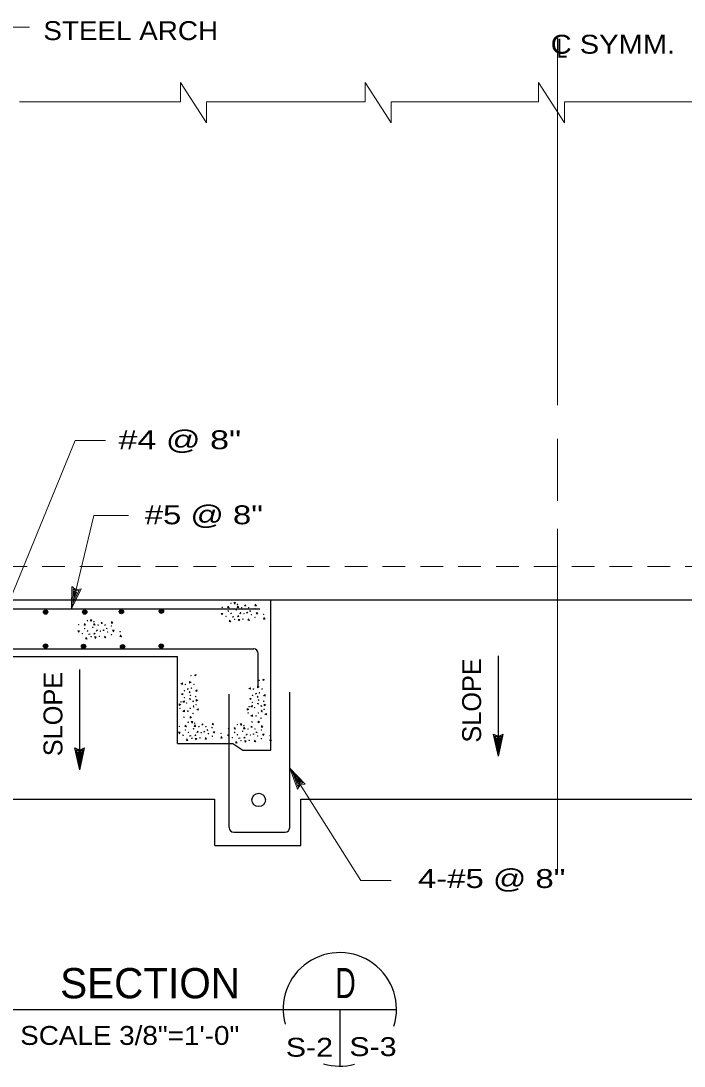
# Model space of a CAD drawing. Extents: x -28.1 to 13.9, y -16.1 to 13.9.
# Drawn here: x -19.31 to -14.93, y -7.92 to -1.02 of the extents above; entities that cross this region are included whole.
import ezdxf
from ezdxf.enums import TextEntityAlignment as Align

# ---------------------------------------------------------------- set-up
doc = ezdxf.new("R2010")
doc.units = 0
doc.header["$LTSCALE"] = 0.05
doc.linetypes.add('MEDIUM_DASHED', pattern=[4.5, 3, -1.5])
doc.layers.add('1', color=7, linetype='Continuous', lineweight=13)
doc.layers.add('2', color=7, linetype='Continuous', lineweight=13)

msp = doc.modelspace()

# ---------------------------------------------------------------- linework, layer by layer
at = {"layer": '1'}
for p, q in [((-15.76204, -3.55531), (-15.76204, -1.13031)), ((-18.25304, -1.55131), (-18.25304, -1.42331)), ((-18.08104, -1.68931), (-18.25304, -1.42331)), ((-17.03304, -1.55131), (-17.03304, -1.42331)), ((-16.86104, -1.68931), (-17.03304, -1.42331)), ((-15.88704, -1.55131), (-15.88704, -1.42331)), ((-15.71504, -1.68931), (-15.88704, -1.42331)), ((-18.25304, -1.55131), (-19.31704, -1.55131)), ((-18.08104, -1.68931), (-18.08104, -1.55131)), ((-17.03304, -1.55131), (-18.08104, -1.55131)), ((-16.86104, -1.68931), (-16.86104, -1.55131)), ((-15.88704, -1.55131), (-16.86104, -1.55131)), ((-15.71504, -1.68931), (-15.71504, -1.55131)), ((-14.65104, -1.55131), (-15.71504, -1.55131)), ((-19.39304, -4.87031), (-18.95004, -3.78931)), ((-18.95004, -3.78931), (-18.75004, -3.78931)), ((-15.76204, -4.18731), (-15.76204, -3.77831)), ((-18.97404, -4.90231), (-18.82604, -4.28531)), ((-18.82604, -4.28531), (-18.59704, -4.28531)), ((-15.76204, -6.64831), (-15.76204, -4.37331)), ((-18.97404, -4.90231), (-18.97104, -4.75531)), ((-18.97404, -4.90231), (-18.91004, -4.76931)), ((-18.96504, -4.86631), (-18.96304, -4.77031)), ((-18.96504, -4.86631), (-18.92404, -4.77931)), ((-18.96304, -4.77031), (-18.94604, -4.78331)), ((-18.95704, -4.83131), (-18.95604, -4.78531)), ((-18.95704, -4.83131), (-18.93804, -4.78931)), ((-18.95604, -4.78531), (-18.94704, -4.79131)), ((-18.94704, -4.79131), (-18.93804, -4.78931)), ((-18.94604, -4.78331), (-18.92404, -4.77931)), ((-17.53204, -5.95531), (-17.42904, -6.06031)), ((-17.53204, -5.95531), (-17.48104, -6.09331)), ((-17.51204, -5.98631), (-17.44504, -6.05531)), ((-17.51204, -5.98631), (-17.47904, -6.07631)), ((-17.49304, -6.01731), (-17.47604, -6.05931)), ((-17.49304, -6.01731), (-17.46004, -6.04931)), ((-17.46704, -6.05831), (-17.47904, -6.07631)), ((-17.47104, -6.05131), (-17.47604, -6.05931)), ((-17.46004, -6.04931), (-17.47104, -6.05131)), ((-17.44504, -6.05531), (-17.46704, -6.05831))]:
    msp.add_line(p, q, dxfattribs=at)
at = {"layer": '1', "linetype": 'MEDIUM_DASHED'}
msp.add_line((-20.41804, -4.62131), (-12.68204, -4.62131), dxfattribs=at)
at = {"layer": '1', "lineweight": 25}
for p, q in [((-21.29204, -4.84331), (-12.68604, -4.84331)), ((-20.51304, -4.90231), (-17.72904, -4.90231)), ((-17.65604, -5.83731), (-17.65604, -4.84331)), ((-21.29604, -5.16731), (-17.77004, -5.16731)), ((-23.96004, -5.21731), (-18.27404, -5.21731)), ((-18.27404, -5.79331), (-18.27404, -5.21731)), ((-17.74004, -5.41431), (-17.74004, -5.19731)), ((-16.15304, -5.87531), (-16.15304, -5.21231)), ((-18.92004, -5.96531), (-18.92004, -5.30231)), ((-17.53204, -6.34831), (-17.53204, -5.45231)), ((-17.93204, -6.34831), (-17.93204, -5.46631)), ((-16.15304, -5.87531), (-16.18404, -5.73131)), ((-16.15304, -5.87531), (-16.12204, -5.73131)), ((-18.27404, -5.79331), (-17.90704, -5.79331)), ((-17.90704, -5.79331), (-17.84104, -5.83731)), ((-16.15304, -5.83831), (-16.17304, -5.74431)), ((-16.17304, -5.74431), (-16.15304, -5.75331)), ((-16.15304, -5.80231), (-16.16304, -5.75731)), ((-16.16304, -5.75731), (-16.15304, -5.76131)), ((-16.15304, -5.83831), (-16.13304, -5.74431)), ((-16.15304, -5.75331), (-16.13304, -5.74431)), ((-16.15304, -5.80231), (-16.14404, -5.75731)), ((-16.15304, -5.76131), (-16.14404, -5.75731)), ((-18.92004, -5.96531), (-18.95104, -5.82131)), ((-18.92004, -5.92831), (-18.94004, -5.83431)), ((-18.94004, -5.83431), (-18.92004, -5.84331)), ((-18.92004, -5.89231), (-18.93004, -5.84731)), ((-18.93004, -5.84731), (-18.92004, -5.85131)), ((-18.92004, -5.96531), (-18.88904, -5.82131)), ((-18.92004, -5.92831), (-18.90004, -5.83431)), ((-18.92004, -5.84331), (-18.90004, -5.83431)), ((-18.92004, -5.89231), (-18.91104, -5.84731)), ((-18.92004, -5.85131), (-18.91104, -5.84731)), ((-17.84104, -5.83731), (-17.65604, -5.83731)), ((-21.29004, -6.16031), (-18.02804, -6.16031)), ((-18.02704, -6.46731), (-18.02704, -6.16031)), ((-17.90204, -6.37831), (-17.56204, -6.37831)), ((-18.02704, -6.46731), (-17.45804, -6.46731)), ((-19.53504, -7.54931), (-16.82604, -7.54931)), ((-17.20104, -7.54931), (-17.20104, -7.92431))]:
    msp.add_line(p, q, dxfattribs=at)
at = {"layer": '1'}
for points in [[(-20.42404, -2.50931), (-19.52504, -1.05831), (-19.25104, -1.05831)], [(-18.97104, -4.75531), (-18.94404, -4.77631), (-18.91004, -4.76931)], [(-17.53204, -5.95531), (-17.06104, -6.69731), (-16.86204, -6.69731)], [(-17.42904, -6.06031), (-17.46204, -6.06531), (-17.48104, -6.09331)]]:
    msp.add_lwpolyline(points, dxfattribs=at)
at = {"layer": '1', "lineweight": 25}
for points in [[(-16.18404, -5.73131), (-16.15304, -5.74531), (-16.12204, -5.73131)], [(-18.95104, -5.82131), (-18.92004, -5.83531), (-18.88904, -5.82131)], [(-17.45804, -6.46731), (-17.45804, -6.16031), (-14.06804, -6.16031)]]:
    msp.add_lwpolyline(points, dxfattribs=at)
for centre, radius in [((-18.37957, -4.91759), 0.01445), ((-19.14557, -4.92359), 0.01445), ((-19.14557, -4.92359), 0.01121), ((-19.14557, -4.92359), 0.00822), ((-19.14557, -4.92359), 0.00415), ((-18.88657, -4.92359), 0.01445), ((-18.88657, -4.92359), 0.01121), ((-18.88657, -4.92359), 0.00822), ((-18.88657, -4.92359), 0.00415), ((-18.64457, -4.92059), 0.01445), ((-18.64457, -4.92059), 0.01121), ((-18.64457, -4.92059), 0.00822), ((-18.64457, -4.92059), 0.00415), ((-18.37957, -4.91759), 0.01121), ((-18.37957, -4.91759), 0.00822), ((-18.37957, -4.91759), 0.00415), ((-19.14557, -5.14859), 0.01445), ((-19.14557, -5.14859), 0.01121), ((-19.14557, -5.14859), 0.00822), ((-19.14557, -5.14859), 0.00415), ((-18.89457, -5.15059), 0.01445), ((-18.89457, -5.15059), 0.01121), ((-18.89457, -5.15059), 0.00822), ((-18.89457, -5.15059), 0.00415), ((-18.63657, -5.15259), 0.01445), ((-18.63657, -5.15259), 0.01121), ((-18.63657, -5.15259), 0.00822), ((-18.63657, -5.15259), 0.00415), ((-18.38057, -5.14859), 0.01445), ((-18.38057, -5.14859), 0.01121), ((-18.38057, -5.14859), 0.00822), ((-18.38057, -5.14859), 0.00415), ((-17.73704, -6.16531), 0.04428)]:
    msp.add_circle(centre, radius, dxfattribs=at)
for centre, radius, start, end in [((-17.77004, -5.19731), 0.03, 0, 90), ((-17.90204, -6.34831), 0.03, 180, 270), ((-17.56204, -6.34831), 0.03, 270, 0), ((-17.20104, -7.54931), 0.375, 342.70891, 195.26862), ((-17.20104, -7.54931), 0.375, 253.4742, 284.92162)]:
    msp.add_arc(centre, radius, start, end, dxfattribs=at)
at = {"layer": '2'}
for p, q in [((-17.83004, -4.88131), (-17.82404, -4.87631)), ((-18.77904, -4.99631), (-18.77304, -4.99131)), ((-18.24104, -5.47031), (-18.24604, -5.46431)), ((-17.79104, -5.50131), (-17.79604, -5.49531)), ((-18.11304, -5.66731), (-18.10704, -5.66231)), ((-17.78804, -5.68331), (-17.78204, -5.67831))]:
    msp.add_line(p, q, dxfattribs=at)
for points in [[(-17.93704, -4.88431), (-17.94204, -4.89431), (-17.93204, -4.89531), (-17.94004, -4.88431)], [(-17.89604, -4.86931), (-17.90104, -4.86031), (-17.89004, -4.86031), (-17.89604, -4.87131)], [(-17.87504, -4.88331), (-17.88004, -4.89331), (-17.86904, -4.89431), (-17.87704, -4.88331)], [(-17.82404, -4.87631), (-17.82204, -4.88331), (-17.83004, -4.88331)], [(-17.75704, -4.87131), (-17.76204, -4.88131), (-17.75204, -4.88231), (-17.76004, -4.87131)], [(-17.97904, -4.94031), (-17.98404, -4.93231), (-17.97304, -4.93231), (-17.97904, -4.94231)], [(-17.91004, -4.95531), (-17.90504, -4.95231), (-17.90104, -4.95531), (-17.91304, -4.95731)], [(-17.86804, -4.98131), (-17.87304, -4.97231), (-17.86204, -4.97231), (-17.86804, -4.98231)], [(-17.81704, -4.92931), (-17.81404, -4.92531), (-17.80904, -4.92931), (-17.81604, -4.93031)], [(-17.80304, -4.96731), (-17.80804, -4.97731), (-17.79804, -4.97831), (-17.80604, -4.96731)], [(-17.79704, -4.91631), (-17.79204, -4.91431), (-17.78904, -4.92031), (-17.79704, -4.91731)], [(-17.74904, -4.93631), (-17.75404, -4.92831), (-17.74304, -4.92831), (-17.74904, -4.93831)], [(-17.70004, -4.96031), (-17.70504, -4.97031), (-17.69504, -4.97131), (-17.70204, -4.96031)], [(-18.88604, -4.99931), (-18.89104, -5.00931), (-18.88104, -5.01031), (-18.88904, -4.99931)], [(-18.84504, -4.98431), (-18.85004, -4.97531), (-18.83904, -4.97531), (-18.84504, -4.98631)], [(-18.82404, -4.99831), (-18.82904, -5.00831), (-18.81804, -5.00931), (-18.82604, -4.99831)], [(-18.77304, -4.99131), (-18.77104, -4.99831), (-18.77904, -4.99831)], [(-18.76604, -5.04431), (-18.76304, -5.04031), (-18.75804, -5.04431), (-18.76504, -5.04531)], [(-18.74604, -5.03131), (-18.74104, -5.02931), (-18.73804, -5.03531), (-18.74604, -5.03231)], [(-18.70604, -4.98631), (-18.71104, -4.99631), (-18.70104, -4.99731), (-18.70904, -4.98631)], [(-17.92704, -4.97631), (-17.93204, -4.98631), (-17.92204, -4.98731), (-17.93004, -4.97631)], [(-18.92804, -5.05531), (-18.93304, -5.04731), (-18.92204, -5.04731), (-18.92804, -5.05731)], [(-18.87604, -5.09131), (-18.88104, -5.10131), (-18.87104, -5.10231), (-18.87904, -5.09131)], [(-18.85904, -5.07031), (-18.85404, -5.06731), (-18.85004, -5.07031), (-18.86204, -5.07231)], [(-18.81704, -5.09631), (-18.82204, -5.08731), (-18.81104, -5.08731), (-18.81704, -5.09731)], [(-18.75204, -5.08231), (-18.75704, -5.09231), (-18.74704, -5.09331), (-18.75504, -5.08231)], [(-18.69804, -5.05131), (-18.70304, -5.04331), (-18.69204, -5.04331), (-18.69804, -5.05331)], [(-18.64904, -5.07531), (-18.65404, -5.08531), (-18.64404, -5.08631), (-18.65104, -5.07531)], [(-18.18604, -5.38931), (-18.19404, -5.39431), (-18.19404, -5.38331), (-18.18404, -5.38931)], [(-18.16204, -5.34031), (-18.15204, -5.34531), (-18.15104, -5.33531), (-18.16204, -5.34231)], [(-17.71204, -5.37131), (-17.70204, -5.37631), (-17.70104, -5.36631), (-17.71204, -5.37331)], [(-18.25104, -5.39731), (-18.24104, -5.40231), (-18.24004, -5.39231), (-18.25104, -5.40031)], [(-18.20604, -5.43731), (-18.20804, -5.43231), (-18.20204, -5.42931), (-18.20504, -5.43731)], [(-18.19304, -5.45731), (-18.19704, -5.45431), (-18.19304, -5.44931), (-18.19204, -5.45631)], [(-18.15504, -5.44331), (-18.14504, -5.44831), (-18.14404, -5.43831), (-18.15504, -5.44631)], [(-17.80104, -5.42831), (-17.79104, -5.43331), (-17.79004, -5.42331), (-17.80104, -5.43131)], [(-17.73604, -5.42031), (-17.74404, -5.42531), (-17.74404, -5.41431), (-17.73404, -5.42031)], [(-18.24604, -5.46431), (-18.23904, -5.46231), (-18.23904, -5.47031)], [(-18.23904, -5.51531), (-18.22904, -5.52031), (-18.22804, -5.50931), (-18.23904, -5.51731)], [(-18.14104, -5.50831), (-18.15004, -5.51331), (-18.15004, -5.50231), (-18.14004, -5.50831)], [(-17.79604, -5.49531), (-17.78904, -5.49331), (-17.78904, -5.50131)], [(-17.75604, -5.46831), (-17.75804, -5.46331), (-17.75204, -5.46031), (-17.75504, -5.46831)], [(-17.74304, -5.48831), (-17.74704, -5.48531), (-17.74304, -5.48031), (-17.74204, -5.48731)], [(-17.70504, -5.47431), (-17.69504, -5.47931), (-17.69404, -5.46931), (-17.70504, -5.47731)], [(-18.25304, -5.53631), (-18.26204, -5.54131), (-18.26204, -5.53031), (-18.25104, -5.53631)], [(-18.23804, -5.57731), (-18.22804, -5.58231), (-18.22704, -5.57231), (-18.23804, -5.58031)], [(-18.16704, -5.55031), (-18.17004, -5.54531), (-18.16704, -5.54131), (-18.16504, -5.55331)], [(-18.14604, -5.56731), (-18.13604, -5.57231), (-18.13504, -5.56231), (-18.14604, -5.57031)], [(-17.80304, -5.56731), (-17.81204, -5.57231), (-17.81204, -5.56131), (-17.80104, -5.56731)], [(-17.78904, -5.54631), (-17.77904, -5.55131), (-17.77804, -5.54031), (-17.78904, -5.54831)], [(-17.71704, -5.58131), (-17.72004, -5.57631), (-17.71704, -5.57231), (-17.71504, -5.58431)], [(-17.69104, -5.53931), (-17.70004, -5.54431), (-17.70004, -5.53331), (-17.69004, -5.53931)], [(-17.69604, -5.59831), (-17.68604, -5.60331), (-17.68504, -5.59331), (-17.69604, -5.60131)], [(-18.18204, -5.61931), (-18.19004, -5.62431), (-18.19004, -5.61331), (-18.18004, -5.61931)], [(-18.17904, -5.65531), (-18.18404, -5.64631), (-18.17304, -5.64631), (-18.17904, -5.65731)], [(-18.10704, -5.66231), (-18.10504, -5.66931), (-18.11304, -5.66931)], [(-18.04004, -5.65731), (-18.04504, -5.66731), (-18.03504, -5.66831), (-18.04304, -5.65731)], [(-17.85404, -5.67131), (-17.85904, -5.66231), (-17.84804, -5.66231), (-17.85404, -5.67331)], [(-17.78804, -5.60831), (-17.77804, -5.61331), (-17.77704, -5.60331), (-17.78804, -5.61131)], [(-17.73204, -5.65031), (-17.74004, -5.65531), (-17.74004, -5.64431), (-17.73004, -5.65031)], [(-18.26204, -5.72631), (-18.26704, -5.71831), (-18.25604, -5.71831), (-18.26204, -5.72831)], [(-18.22004, -5.67031), (-18.22504, -5.68031), (-18.21504, -5.68131), (-18.22304, -5.67031)], [(-18.15804, -5.66931), (-18.16304, -5.67931), (-18.15204, -5.68031), (-18.16004, -5.66931)], [(-18.10004, -5.71531), (-18.09704, -5.71131), (-18.09204, -5.71531), (-18.09904, -5.71631)], [(-18.08004, -5.70231), (-18.07504, -5.70031), (-18.07204, -5.70631), (-18.08004, -5.70331)], [(-18.03204, -5.72231), (-18.03704, -5.71431), (-18.02604, -5.71431), (-18.03204, -5.72431)], [(-17.89504, -5.68631), (-17.90004, -5.69631), (-17.89004, -5.69731), (-17.89804, -5.68631)], [(-17.83304, -5.68531), (-17.83804, -5.69531), (-17.82704, -5.69631), (-17.83504, -5.68531)], [(-17.78204, -5.67831), (-17.78004, -5.68531), (-17.78804, -5.68531)], [(-17.77504, -5.73131), (-17.77204, -5.72731), (-17.76704, -5.73131), (-17.77404, -5.73231)], [(-17.75504, -5.71831), (-17.75004, -5.71631), (-17.74704, -5.72231), (-17.75504, -5.71931)], [(-17.71504, -5.67331), (-17.72004, -5.68331), (-17.71004, -5.68431), (-17.71804, -5.67331)], [(-17.70704, -5.73831), (-17.71204, -5.73031), (-17.70104, -5.73031), (-17.70704, -5.74031)], [(-18.21004, -5.76231), (-18.21504, -5.77231), (-18.20504, -5.77331), (-18.21304, -5.76231)], [(-18.19304, -5.74131), (-18.18804, -5.73831), (-18.18404, -5.74131), (-18.19604, -5.74331)], [(-18.15104, -5.76731), (-18.15604, -5.75831), (-18.14504, -5.75831), (-18.15104, -5.76831)], [(-18.08604, -5.75331), (-18.09104, -5.76331), (-18.08104, -5.76431), (-18.08904, -5.75331)], [(-17.98304, -5.74631), (-17.98804, -5.75631), (-17.97804, -5.75731), (-17.98504, -5.74631)], [(-17.93704, -5.74231), (-17.94204, -5.73431), (-17.93104, -5.73431), (-17.93704, -5.74431)], [(-17.88504, -5.77831), (-17.89004, -5.78831), (-17.88004, -5.78931), (-17.88804, -5.77831)], [(-17.86804, -5.75731), (-17.86304, -5.75431), (-17.85904, -5.75731), (-17.87104, -5.75931)], [(-17.82604, -5.78331), (-17.83104, -5.77431), (-17.82004, -5.77431), (-17.82604, -5.78431)], [(-17.76104, -5.76931), (-17.76604, -5.77931), (-17.75604, -5.78031), (-17.76404, -5.76931)], [(-17.65804, -5.76231), (-17.66304, -5.77231), (-17.65304, -5.77331), (-17.66004, -5.76231)]]:
    msp.add_lwpolyline(points, dxfattribs=at)
for points in [[(-17.87704, -4.95531), (-17.87204, -4.94731), (-17.86904, -4.95331)], [(-17.86204, -4.93431), (-17.85704, -4.92531), (-17.85404, -4.93131)], [(-18.81104, -5.04931), (-18.80604, -5.04031), (-18.80304, -5.04631)], [(-18.82604, -5.07031), (-18.82104, -5.06231), (-18.81804, -5.06831)], [(-18.18804, -5.50231), (-18.19704, -5.49731), (-18.19104, -5.49431)], [(-18.16704, -5.51731), (-18.17504, -5.51231), (-18.16904, -5.50931)], [(-17.73804, -5.53331), (-17.74704, -5.52831), (-17.74104, -5.52531)], [(-17.71704, -5.54831), (-17.72504, -5.54331), (-17.71904, -5.54031)], [(-18.16004, -5.74131), (-18.15504, -5.73331), (-18.15204, -5.73931)], [(-18.14504, -5.72031), (-18.14004, -5.71131), (-18.13704, -5.71731)], [(-17.82004, -5.73631), (-17.81504, -5.72731), (-17.81204, -5.73331)], [(-17.83504, -5.75731), (-17.83004, -5.74931), (-17.82704, -5.75531)]]:
    msp.add_lwpolyline(points, close=True, dxfattribs=at)
for centre in [(-17.97804, -4.89219), (-17.91979, -4.86544), (-17.87704, -4.87219), (-17.84929, -4.89394), (-17.80304, -4.89494), (-17.76179, -4.90069), (-17.95354, -4.95119), (-17.93829, -4.91744), (-17.91904, -4.93269), (-17.89554, -4.97144), (-17.88454, -4.90919), (-17.84154, -4.96894), (-17.83404, -4.93444), (-17.78604, -4.94019), (-17.76079, -4.95794), (-17.70354, -4.93844), (-18.92704, -5.00719), (-18.88729, -5.03244), (-18.86879, -4.98044), (-18.83354, -5.02419), (-18.82604, -4.98719), (-18.79829, -5.00894), (-18.75204, -5.00994), (-18.71079, -5.01569), (-18.90254, -5.06619), (-18.86804, -5.04769), (-18.84454, -5.08644), (-18.79054, -5.08394), (-18.78304, -5.04944), (-18.73504, -5.05519), (-18.70979, -5.07294), (-18.65254, -5.05344), (-18.18392, -5.34381), (-17.73392, -5.37481), (-18.22742, -5.44331), (-18.22167, -5.40206), (-18.18217, -5.42631), (-18.16442, -5.40106), (-17.77167, -5.43306), (-17.73217, -5.45731), (-17.71442, -5.43206), (-18.25017, -5.51731), (-18.22842, -5.48956), (-18.21317, -5.52481), (-18.18792, -5.47431), (-18.15342, -5.48181), (-17.77842, -5.52056), (-17.77742, -5.47431), (-17.73792, -5.50531), (-17.70342, -5.51281), (-18.25692, -5.56006), (-18.20492, -5.57856), (-18.18967, -5.55931), (-18.17117, -5.59381), (-18.15092, -5.53581), (-17.80692, -5.59106), (-17.80017, -5.54831), (-17.76317, -5.55581), (-17.73967, -5.59031), (-17.70092, -5.56681), (-18.23017, -5.61831), (-18.20279, -5.65144), (-18.16004, -5.65819), (-17.78017, -5.64931), (-17.75492, -5.60956), (-17.72117, -5.62481), (-18.26104, -5.67819), (-18.22129, -5.70344), (-18.20204, -5.71869), (-18.16754, -5.69519), (-18.13229, -5.67994), (-18.11704, -5.72044), (-18.08604, -5.68094), (-18.06904, -5.72619), (-18.04479, -5.68669), (-17.98654, -5.72444), (-17.93604, -5.69419), (-17.89629, -5.71944), (-17.87779, -5.66744), (-17.87704, -5.73469), (-17.84254, -5.71119), (-17.83504, -5.67419), (-17.80729, -5.69594), (-17.76104, -5.69694), (-17.71979, -5.70269), (-18.23654, -5.73719), (-18.17854, -5.75744), (-18.12454, -5.75494), (-18.04379, -5.74394), (-17.91154, -5.75319), (-17.85354, -5.77344), (-17.79954, -5.77094), (-17.79204, -5.73644), (-17.74404, -5.74219), (-17.71879, -5.75994), (-17.66154, -5.74044)]:
    msp.add_circle(centre, 0.00162, dxfattribs=at)

# ---------------------------------------------------------------- texts
at = {"layer": '1'}
for s, width, p in [('STEEL ARCH', 1.1, (-19.16004, -1.14331)), ('C SYMM.', 1.15, (-15.80704, -1.23331)), ('L', 0.75, (-15.76604, -1.25931)), ('#4 @ 8"', 1.35, (-18.66404, -3.84731)), ('#5 @ 8"', 1.3, (-18.49004, -4.34331)), ('4-#5 @ 8"', 1.3, (-16.68404, -6.74731)), ('SCALE 3/8"=1\'-0"', 1.1, (-19.31304, -7.78431))]:
    msp.add_text(s, height=0.125, dxfattribs=dict(at, width=width)).set_placement(p)
for p in [(-16.26704, -5.50745), (-19.03404, -5.59745)]:
    msp.add_text('SLOPE', height=0.125, rotation=90, dxfattribs=at).set_placement(p, align=Align.CENTER)
msp.add_text('SECTION', height=0.2, dxfattribs=at).set_placement((-18.45464, -7.47631), align=Align.CENTER)
for s, height, width, p in [('D', 0.2, 0.7, (-17.1629, -7.47531)), ('S-2', 0.125, 1.2, (-17.40168, -7.86231)), ('S-3', 0.125, 1.2, (-16.98168, -7.85831))]:
    msp.add_text(s, height=height, dxfattribs=dict(at, width=width)).set_placement(p, align=Align.CENTER)

doc.saveas('drawing.dxf')
